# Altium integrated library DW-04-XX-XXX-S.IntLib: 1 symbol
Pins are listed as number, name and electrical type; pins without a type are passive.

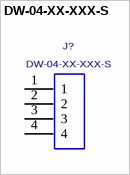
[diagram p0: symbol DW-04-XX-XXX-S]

## DW-04-XX-XXX-S
designator J?
LOW COST BAORD SPACERS.; MANUFACTURER: SAMTEC
footprint DW-04-XX-XXX-S
pins: 1, 2, 3, 4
